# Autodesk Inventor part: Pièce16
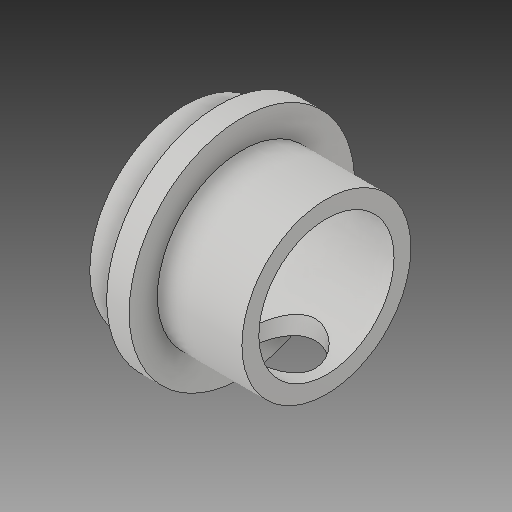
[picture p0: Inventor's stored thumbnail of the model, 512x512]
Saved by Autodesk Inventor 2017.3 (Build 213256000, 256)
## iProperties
Created: 2007-11
Part Number: Pièce16
Material: Générique
Document SubType Name: Modeling
Designer: ficho
Density: 1 g/cm^3
Appearance: Par défaut
Author: ficho
Sending System: SolidWorks 2009
Last Author: christophe
Last Saved: 2011-02-10
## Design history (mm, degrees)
feature "Enlèv. mat.-Extru.3"
node "Solide1"
